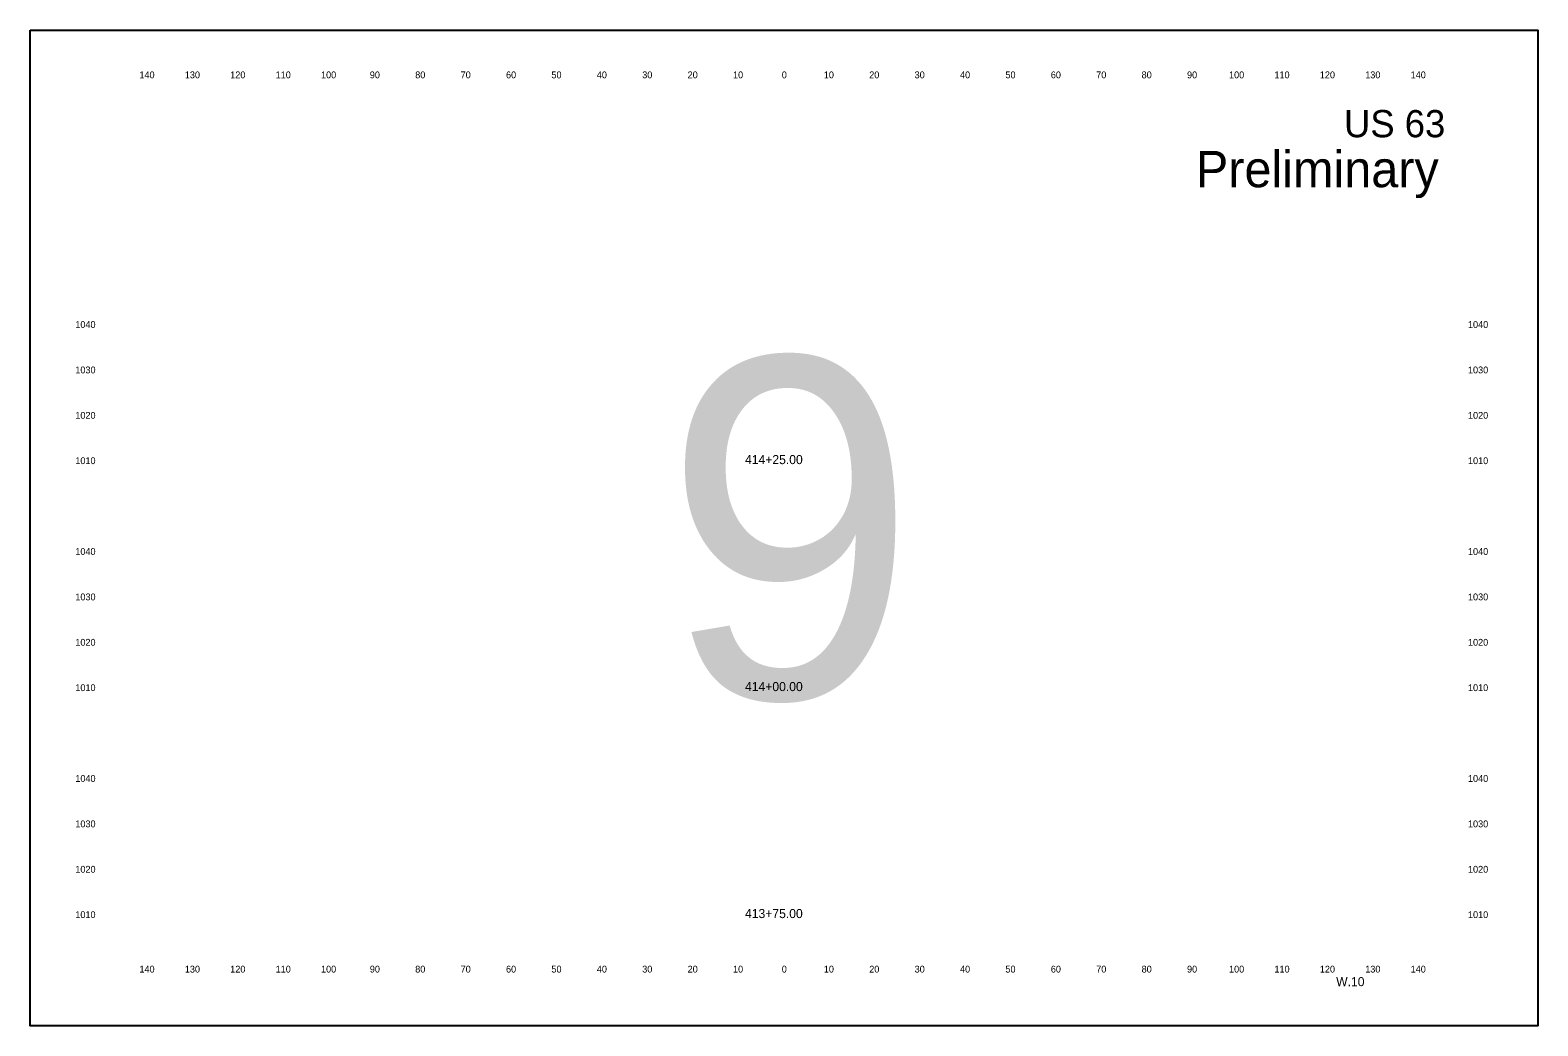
# Model space of a CAD drawing. Extents: x 10123 to 17295, y 9730 to 10181.
# Drawn here: x 13003.2 to 13335.3, y 9730.3 to 9949.6 of the extents above; entities that cross this region are included whole.
import ezdxf

# ---------------------------------------------------------------- set-up
doc = ezdxf.new("R2010")
doc.units = 0
for name, color, linetype in [('dsnTextCpn', 7, 'Continuous'), ('dsnTextCpnTitleSheetLocDesc', 7, 'Continuous'), ('dsnTextCpnTitleSheetPIN', 7, 'Continuous'), ('dsnTextCpnTitleSheetWorkType', 7, 'Continuous')]:
    doc.layers.add(name, color=color, linetype=linetype)

msp = doc.modelspace()

# ---------------------------------------------------------------- linework, layer by layer
at = {"layer": 'dsnTextCpnTitleSheetWorkType'}
msp.add_lwpolyline([(13003.21, 9949.6), (13335.29, 9949.6), (13335.29, 9730.26), (13003.21, 9730.26)], close=True, dxfattribs=at)

# ---------------------------------------------------------------- texts
at = {"layer": 'dsnTextCpn'}
for s, height, p in [('140', 1.5, (13027.27, 9939)), ('130', 1.5, (13037.27, 9939)), ('120', 1.5, (13047.27, 9939)), ('110', 1.5, (13057.27, 9939)), ('100', 1.5, (13067.27, 9939)), ('90', 1.5, (13078.02, 9939)), ('80', 1.5, (13088.02, 9939)), ('70', 1.5, (13098.02, 9939)), ('60', 1.5, (13108.02, 9939)), ('50', 1.5, (13118.02, 9939)), ('40', 1.5, (13128.02, 9939)), ('30', 1.5, (13138.02, 9939)), ('20', 1.5, (13148.02, 9939)), ('10', 1.5, (13158.02, 9939)), ('0', 1.5, (13168.76, 9939)), ('0', 1.5, (13168.76, 9939)), ('10', 1.5, (13178.02, 9939)), ('20', 1.5, (13188.02, 9939)), ('30', 1.5, (13198.02, 9939)), ('40', 1.5, (13208.02, 9939)), ('50', 1.5, (13218.02, 9939)), ('60', 1.5, (13228.02, 9939)), ('70', 1.5, (13238.02, 9939)), ('80', 1.5, (13248.02, 9939)), ('90', 1.5, (13258.02, 9939)), ('100', 1.5, (13267.27, 9939)), ('110', 1.5, (13277.27, 9939)), ('120', 1.5, (13287.27, 9939)), ('130', 1.5, (13297.27, 9939)), ('140', 1.5, (13307.27, 9939)), ('US 63', 6, (13292.6, 9926)), ('1040', 1.5, (13013.15, 9884)), ('1040', 1.5, (13319.9, 9884)), ('1030', 1.5, (13013.15, 9874)), ('1030', 1.5, (13319.9, 9874)), ('1020', 1.5, (13013.15, 9864)), ('1020', 1.5, (13319.9, 9864)), ('1010', 1.5, (13013.15, 9854)), ('414+25.00', 2, (13160.66, 9854)), ('1010', 1.5, (13319.9, 9854)), ('1040', 1.5, (13013.15, 9834)), ('1040', 1.5, (13319.9, 9834)), ('1030', 1.5, (13013.15, 9824)), ('1030', 1.5, (13319.9, 9824)), ('1020', 1.5, (13013.15, 9814)), ('1020', 1.5, (13319.9, 9814)), ('1010', 1.5, (13013.15, 9804)), ('414+00.00', 2, (13160.66, 9804)), ('1010', 1.5, (13319.9, 9804)), ('1040', 1.5, (13013.15, 9784)), ('1040', 1.5, (13319.9, 9784)), ('1030', 1.5, (13013.15, 9774)), ('1030', 1.5, (13319.9, 9774)), ('1020', 1.5, (13013.15, 9764)), ('1020', 1.5, (13319.9, 9764)), ('1010', 1.5, (13013.15, 9754)), ('413+75.00', 2, (13160.66, 9754)), ('1010', 1.5, (13319.9, 9754)), ('140', 1.5, (13027.27, 9742)), ('130', 1.5, (13037.27, 9742)), ('120', 1.5, (13047.27, 9742)), ('110', 1.5, (13057.27, 9742)), ('100', 1.5, (13067.27, 9742)), ('90', 1.5, (13078.02, 9742)), ('80', 1.5, (13088.02, 9742)), ('70', 1.5, (13098.02, 9742)), ('60', 1.5, (13108.02, 9742)), ('50', 1.5, (13118.02, 9742)), ('40', 1.5, (13128.02, 9742)), ('30', 1.5, (13138.02, 9742)), ('20', 1.5, (13148.02, 9742)), ('10', 1.5, (13158.02, 9742)), ('0', 1.5, (13168.76, 9742)), ('0', 1.5, (13168.76, 9742)), ('10', 1.5, (13178.02, 9742)), ('20', 1.5, (13188.02, 9742)), ('30', 1.5, (13198.02, 9742)), ('40', 1.5, (13208.02, 9742)), ('50', 1.5, (13218.02, 9742)), ('60', 1.5, (13228.02, 9742)), ('70', 1.5, (13238.02, 9742)), ('80', 1.5, (13248.02, 9742)), ('90', 1.5, (13258.02, 9742)), ('100', 1.5, (13267.27, 9742)), ('110', 1.5, (13277.27, 9742)), ('120', 1.5, (13287.27, 9742)), ('130', 1.5, (13297.27, 9742)), ('140', 1.5, (13307.27, 9742))]:
    msp.add_text(s, height=height, dxfattribs=at).set_placement(p)
at = {"layer": 'dsnTextCpnTitleSheetLocDesc'}
msp.add_text('Preliminary', height=8, dxfattribs=at).set_placement((13259.97, 9915))
at = {"layer": 'dsnTextCpnTitleSheetPIN'}
msp.add_text('W.10', height=2, dxfattribs=at).set_placement((13290.87, 9739))
at = {"layer": 'dsnTextCpnTitleSheetWorkType'}
msp.add_text('9', height=75, dxfattribs=at).set_placement((13142.74, 9802.43))

doc.saveas('drawing.dxf')
